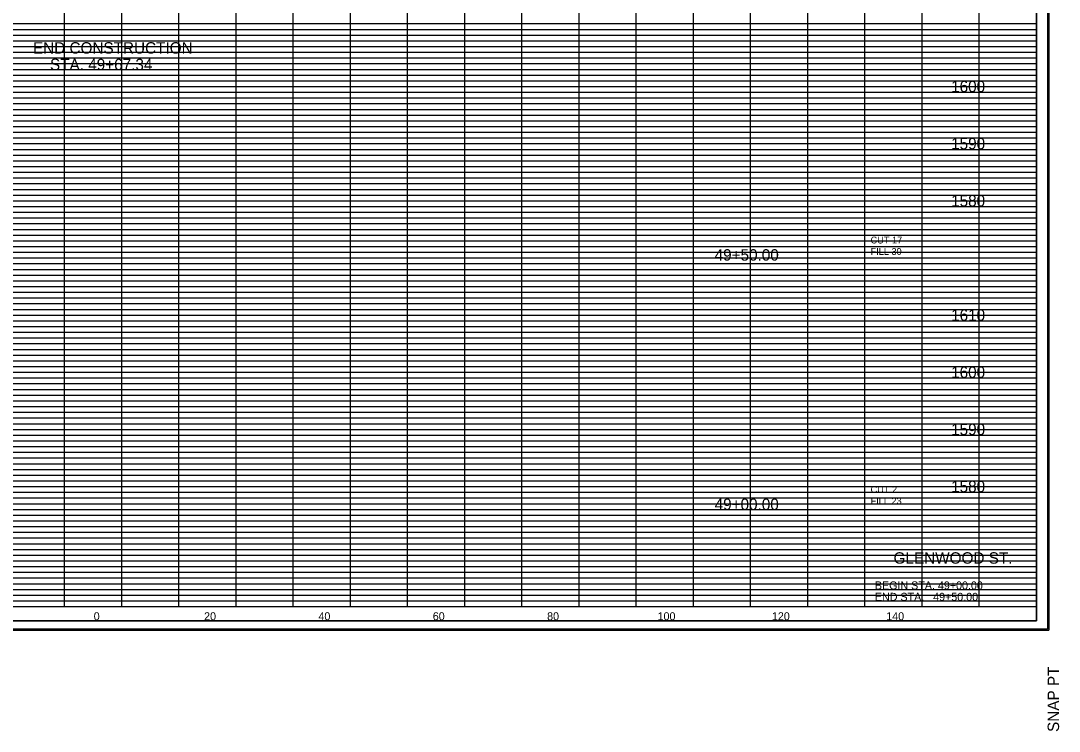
# Model space of a CAD drawing. Extents: x 980 to 1324, y 978 to 1497.
# Drawn here: x 1142.3 to 1324, y 1248.2 to 1372.5 of the extents above; entities that cross this region are included whole.
import ezdxf

# ---------------------------------------------------------------- set-up
doc = ezdxf.new("R2010")
doc.units = 0
for name, color, linetype in [('DESIGN - SHEET - Corner Text', 7, 'Continuous'), ('DESIGN - SHEET - Light Grid', 7, 'Continuous'), ('DESIGN - SHEET - Linework', 7, 'Continuous'), ('DESIGN - SHEET - Plot Shape', 7, 'Continuous'), ('DESIGN - TYPICAL - Text', 7, 'Continuous')]:
    doc.layers.add(name, color=color, linetype=linetype)

# ---------------------------------------------------------------- blocks, each defined once
blk = doc.blocks.new('XSTSHT')
at = {"layer": 'DESIGN - SHEET - Light Grid'}
for p, q in [((8, 10.2), (16, 10.2)), ((16, 10.2), (24, 10.2)), ((24, 10.2), (32, 10.2)), ((8, 10.1), (16, 10.1)), ((16, 10.1), (24, 10.1)), ((24, 10.1), (32, 10.1)), ((8, 9.9), (16, 9.9)), ((16, 9.9), (24, 9.9)), ((24, 9.9), (32, 9.9)), ((8, 9.8), (16, 9.8)), ((8, 9.7), (16, 9.7)), ((16, 9.8), (24, 9.8)), ((16, 9.7), (24, 9.7)), ((24, 9.8), (32, 9.8)), ((24, 9.7), (32, 9.7)), ((8, 9.6), (16, 9.6)), ((8, 9.5), (16, 9.5)), ((16, 9.6), (24, 9.6)), ((16, 9.5), (24, 9.5)), ((24, 9.6), (32, 9.6)), ((24, 9.5), (32, 9.5)), ((8, 9.4), (16, 9.4)), ((8, 9.3), (16, 9.3)), ((16, 9.4), (24, 9.4)), ((16, 9.3), (24, 9.3)), ((24, 9.4), (32, 9.4)), ((24, 9.3), (32, 9.3)), ((8, 9.2), (16, 9.2)), ((8, 9.1), (16, 9.1)), ((16, 9.2), (24, 9.2)), ((16, 9.1), (24, 9.1)), ((24, 9.2), (32, 9.2)), ((24, 9.1), (32, 9.1)), ((8, 8.9), (16, 8.9)), ((8, 8.8), (16, 8.8)), ((16, 8.9), (24, 8.9)), ((16, 8.8), (24, 8.8)), ((24, 8.9), (32, 8.9)), ((24, 8.8), (32, 8.8)), ((8, 8.7), (16, 8.7)), ((8, 8.6), (16, 8.6)), ((16, 8.7), (24, 8.7)), ((16, 8.6), (24, 8.6)), ((24, 8.7), (32, 8.7)), ((24, 8.6), (32, 8.6)), ((8, 8.5), (16, 8.5)), ((8, 8.4), (16, 8.4)), ((16, 8.5), (24, 8.5)), ((16, 8.4), (24, 8.4)), ((24, 8.5), (32, 8.5)), ((24, 8.4), (32, 8.4)), ((8, 8.3), (16, 8.3)), ((8, 8.2), (16, 8.2)), ((16, 8.3), (24, 8.3)), ((16, 8.2), (24, 8.2)), ((24, 8.3), (32, 8.3)), ((24, 8.2), (32, 8.2)), ((8, 8.1), (16, 8.1)), ((16, 8.1), (24, 8.1)), ((24, 8.1), (32, 8.1)), ((8, 7.9), (16, 7.9)), ((16, 7.9), (24, 7.9)), ((24, 7.9), (32, 7.9)), ((8, 7.8), (16, 7.8)), ((8, 7.7), (16, 7.7)), ((16, 7.8), (24, 7.8)), ((16, 7.7), (24, 7.7)), ((24, 7.8), (32, 7.8)), ((24, 7.7), (32, 7.7)), ((8, 7.6), (16, 7.6)), ((8, 7.5), (16, 7.5)), ((16, 7.6), (24, 7.6)), ((16, 7.5), (24, 7.5)), ((24, 7.6), (32, 7.6)), ((24, 7.5), (32, 7.5)), ((8, 7.4), (16, 7.4)), ((8, 7.3), (16, 7.3)), ((16, 7.4), (24, 7.4)), ((16, 7.3), (24, 7.3)), ((24, 7.4), (32, 7.4)), ((24, 7.3), (32, 7.3)), ((8, 7.2), (16, 7.2)), ((8, 7.1), (16, 7.1)), ((16, 7.2), (24, 7.2)), ((16, 7.1), (24, 7.1)), ((24, 7.2), (32, 7.2)), ((24, 7.1), (32, 7.1)), ((8, 6.9), (16, 6.9)), ((8, 6.8), (16, 6.8)), ((16, 6.9), (24, 6.9)), ((16, 6.8), (24, 6.8)), ((24, 6.9), (32, 6.9)), ((24, 6.8), (32, 6.8)), ((8, 6.7), (16, 6.7)), ((8, 6.6), (16, 6.6)), ((16, 6.7), (24, 6.7)), ((16, 6.6), (24, 6.6)), ((24, 6.7), (32, 6.7)), ((24, 6.6), (32, 6.6)), ((8, 6.5), (16, 6.5)), ((8, 6.4), (16, 6.4)), ((16, 6.5), (24, 6.5)), ((16, 6.4), (24, 6.4)), ((24, 6.5), (32, 6.5)), ((24, 6.4), (32, 6.4)), ((8, 6.3), (16, 6.3)), ((8, 6.2), (16, 6.2)), ((16, 6.3), (24, 6.3)), ((16, 6.2), (24, 6.2)), ((24, 6.3), (32, 6.3)), ((24, 6.2), (32, 6.2)), ((8, 6.1), (16, 6.1)), ((16, 6.1), (24, 6.1)), ((24, 6.1), (32, 6.1)), ((8, 5.9), (16, 5.9)), ((16, 5.9), (24, 5.9)), ((24, 5.9), (32, 5.9)), ((8, 5.8), (16, 5.8)), ((8, 5.7), (16, 5.7)), ((16, 5.8), (24, 5.8)), ((16, 5.7), (24, 5.7)), ((24, 5.8), (32, 5.8)), ((24, 5.7), (32, 5.7)), ((8, 5.6), (16, 5.6)), ((8, 5.5), (16, 5.5)), ((16, 5.6), (24, 5.6)), ((16, 5.5), (24, 5.5)), ((24, 5.6), (32, 5.6)), ((24, 5.5), (32, 5.5)), ((8, 5.4), (16, 5.4)), ((8, 5.3), (16, 5.3)), ((16, 5.4), (24, 5.4)), ((16, 5.3), (24, 5.3)), ((24, 5.4), (32, 5.4)), ((24, 5.3), (32, 5.3)), ((8, 5.2), (16, 5.2)), ((8, 5.1), (16, 5.1)), ((16, 5.2), (24, 5.2)), ((16, 5.1), (24, 5.1)), ((24, 5.2), (32, 5.2)), ((24, 5.1), (32, 5.1)), ((8, 4.9), (16, 4.9)), ((8, 4.8), (16, 4.8)), ((16, 4.9), (24, 4.9)), ((16, 4.8), (24, 4.8)), ((24, 4.9), (32, 4.9)), ((24, 4.8), (32, 4.8)), ((8, 4.7), (16, 4.7)), ((8, 4.6), (16, 4.6)), ((16, 4.7), (24, 4.7)), ((16, 4.6), (24, 4.6)), ((24, 4.7), (32, 4.7)), ((24, 4.6), (32, 4.6)), ((8, 4.5), (16, 4.5)), ((8, 4.4), (16, 4.4)), ((16, 4.5), (24, 4.5)), ((16, 4.4), (24, 4.4)), ((24, 4.5), (32, 4.5)), ((24, 4.4), (32, 4.4)), ((8, 4.3), (16, 4.3)), ((8, 4.2), (16, 4.2)), ((16, 4.3), (24, 4.3)), ((16, 4.2), (24, 4.2)), ((24, 4.3), (32, 4.3)), ((24, 4.2), (32, 4.2)), ((8, 4.1), (16, 4.1)), ((16, 4.1), (24, 4.1)), ((24, 4.1), (32, 4.1)), ((8, 3.9), (16, 3.9)), ((16, 3.9), (24, 3.9)), ((24, 3.9), (32, 3.9)), ((8, 3.8), (16, 3.8)), ((8, 3.7), (16, 3.7)), ((16, 3.8), (24, 3.8)), ((16, 3.7), (24, 3.7)), ((24, 3.8), (32, 3.8)), ((24, 3.7), (32, 3.7)), ((8, 3.6), (16, 3.6)), ((8, 3.5), (16, 3.5)), ((16, 3.6), (24, 3.6)), ((16, 3.5), (24, 3.5)), ((24, 3.6), (32, 3.6)), ((24, 3.5), (32, 3.5)), ((8, 3.4), (16, 3.4)), ((8, 3.3), (16, 3.3)), ((16, 3.4), (24, 3.4)), ((16, 3.3), (24, 3.3)), ((24, 3.4), (32, 3.4)), ((24, 3.3), (32, 3.3)), ((8, 3.2), (16, 3.2)), ((8, 3.1), (16, 3.1)), ((16, 3.2), (24, 3.2)), ((16, 3.1), (24, 3.1)), ((24, 3.2), (32, 3.2)), ((24, 3.1), (32, 3.1)), ((8, 2.9), (16, 2.9)), ((8, 2.8), (16, 2.8)), ((16, 2.9), (24, 2.9)), ((16, 2.8), (24, 2.8)), ((24, 2.9), (32, 2.9)), ((24, 2.8), (32, 2.8)), ((8, 2.7), (16, 2.7)), ((8, 2.6), (16, 2.6)), ((16, 2.7), (24, 2.7)), ((16, 2.6), (24, 2.6)), ((24, 2.7), (32, 2.7)), ((24, 2.6), (32, 2.6)), ((8, 2.5), (16, 2.5)), ((8, 2.4), (16, 2.4)), ((16, 2.5), (24, 2.5)), ((16, 2.4), (24, 2.4)), ((24, 2.5), (32, 2.5)), ((24, 2.4), (32, 2.4)), ((8, 2.3), (16, 2.3)), ((8, 2.2), (16, 2.2)), ((16, 2.3), (24, 2.3)), ((16, 2.2), (24, 2.2)), ((24, 2.3), (32, 2.3)), ((24, 2.2), (32, 2.2)), ((8, 2.1), (16, 2.1)), ((16, 2.1), (24, 2.1)), ((24, 2.1), (32, 2.1)), ((8, 1.9), (16, 1.9)), ((16, 1.9), (24, 1.9)), ((24, 1.9), (32, 1.9)), ((8, 1.8), (16, 1.8)), ((8, 1.7), (16, 1.7)), ((16, 1.8), (24, 1.8)), ((16, 1.7), (24, 1.7)), ((24, 1.8), (32, 1.8)), ((24, 1.7), (32, 1.7)), ((8, 1.6), (16, 1.6)), ((8, 1.5), (16, 1.5)), ((16, 1.6), (24, 1.6)), ((16, 1.5), (24, 1.5)), ((24, 1.6), (32, 1.6)), ((24, 1.5), (32, 1.5)), ((8, 1.4), (16, 1.4)), ((8, 1.3), (16, 1.3)), ((16, 1.4), (24, 1.4)), ((16, 1.3), (24, 1.3)), ((24, 1.4), (32, 1.4)), ((24, 1.3), (32, 1.3)), ((8, 1.2), (16, 1.2)), ((8, 1.1), (16, 1.1)), ((16, 1.2), (24, 1.2)), ((16, 1.1), (24, 1.1)), ((24, 1.2), (32, 1.2)), ((24, 1.1), (32, 1.1)), ((8, 0.9), (16, 0.9)), ((8, 0.8), (16, 0.8)), ((16, 0.9), (24, 0.9)), ((16, 0.8), (24, 0.8)), ((24, 0.9), (32, 0.9)), ((24, 0.8), (32, 0.8)), ((8, 0.7), (16, 0.7)), ((8, 0.6), (16, 0.6)), ((16, 0.7), (24, 0.7)), ((16, 0.6), (24, 0.6)), ((24, 0.7), (32, 0.7)), ((24, 0.6), (32, 0.6)), ((8, 0.5), (16, 0.5)), ((8, 0.4), (16, 0.4)), ((16, 0.5), (24, 0.5)), ((16, 0.4), (24, 0.4)), ((24, 0.5), (32, 0.5)), ((24, 0.4), (32, 0.4)), ((8, 0.3), (16, 0.3)), ((8, 0.2), (16, 0.2)), ((16, 0.3), (24, 0.3)), ((16, 0.2), (24, 0.2)), ((24, 0.3), (32, 0.3)), ((24, 0.2), (32, 0.2)), ((8, 0.1), (16, 0.1)), ((16, 0.1), (24, 0.1)), ((24, 0.1), (32, 0.1))]:
    blk.add_line(p, q, dxfattribs=at)
at = {"layer": 'DESIGN - SHEET - Linework'}
for p, q in [((32.217, 21.414), (32.217, -0.414)), ((15, 0), (15, 21)), ((16, 0), (16, 21)), ((17, 0), (17, 21)), ((18, 0), (18, 21)), ((19, 0), (19, 21)), ((20, 0), (20, 21)), ((21, 0), (21, 21)), ((22, 0), (22, 21)), ((23, 0), (23, 21)), ((24, 0), (24, 21)), ((25, 0), (25, 21)), ((26, 0), (26, 21)), ((27, 0), (27, 21)), ((28, 0), (28, 20)), ((29, 0), (29, 20)), ((30, 0), (30, 20)), ((31, 0), (31, 20)), ((0, 10), (32, 10)), ((0, 9), (32, 9)), ((0, 8), (32, 8)), ((0, 7), (32, 7)), ((0, 6), (32, 6)), ((0, 5), (32, 5)), ((0, 4), (32, 4)), ((0, 3), (32, 3)), ((0, 2), (32, 2)), ((0, 1), (32, 1)), ((-1.823, -0.414), (32.217, -0.414))]:
    blk.add_line(p, q, dxfattribs=at)
blk.add_lwpolyline([(0, 21), (0, 0), (32, 0), (32, 21), (0, 21)], dxfattribs=at)
at = {"layer": 'DESIGN - SHEET - Plot Shape'}
for points in [[(-1.803, 21.394), (32.197, 21.394), (32.197, -0.394), (-1.803, -0.394)], [(-0.85, 21), (32, 21), (32, -0.25), (-0.85, -0.25)]]:
    blk.add_lwpolyline(points, close=True, dxfattribs=at)
at = {"layer": 'DESIGN - SHEET - Corner Text'}
blk.add_text('SNAP PT  ', height=0.2, rotation=90, dxfattribs=at).set_placement((32.397, -2.194))

msp = doc.modelspace()

# ---------------------------------------------------------------- linework, layer by layer
at = {"layer": 'DESIGN - SHEET - Plot Shape'}
msp.add_lwpolyline([(991.5, 1267.5), (1320, 1267.5), (1320, 1480), (991.5, 1480)], close=True, dxfattribs=at)

# ---------------------------------------------------------------- block references
at = {"layer": 'DESIGN - TYPICAL - Text', "xscale": 10, "yscale": 10}
msp.add_blockref('XSTSHT', (1000, 1270), dxfattribs=at)

# ---------------------------------------------------------------- texts
at = {"layer": 'DESIGN - SHEET - Corner Text'}
for s, height, p in [('GLENWOOD ST.', 2, (1295.02, 1277.5)), ('BEGIN STA. 49+00.00', 1.4, (1291.75, 1273)), ('END STA.   49+50.00', 1.4, (1291.75, 1271))]:
    msp.add_text(s, height=height, dxfattribs=at).set_placement(p)
at = {"layer": 'DESIGN - TYPICAL - Text'}
for s, height, p in [('END CONSTRUCTION', 2, (1144.48, 1366.75)), ('STA. 49+67.34', 2, (1147.46, 1363.85)), ('     1600     ', 2, (1301.37, 1360)), ('     1590     ', 2, (1301.37, 1350)), ('     1580     ', 2, (1301.37, 1340)), ('CUT 17', 1.2, (1291, 1333.53)), ('     49+50.00     ', 2, (1260, 1330.53)), ('FILL 30', 1.2, (1291, 1331.53)), ('     1610     ', 2, (1301.37, 1320)), ('     1600     ', 2, (1301.37, 1310)), ('     1590     ', 2, (1301.37, 1300)), ('     1580     ', 2, (1301.37, 1290)), ('CUT 2', 1.2, (1291, 1289.89)), ('     49+00.00     ', 2, (1260, 1286.89)), ('FILL 23', 1.2, (1291, 1287.89)), ('     0     ', 1.4, (1152.51, 1267.6)), ('     0     ', 1.4, (1152.51, 1267.6)), ('     20     ', 1.4, (1171.82, 1267.6)), ('     40     ', 1.4, (1191.82, 1267.6)), ('     60     ', 1.4, (1211.82, 1267.6)), ('     80     ', 1.4, (1231.82, 1267.6)), ('     100     ', 1.4, (1251.14, 1267.6)), ('     120     ', 1.4, (1271.14, 1267.6)), ('     140     ', 1.4, (1291.14, 1267.6))]:
    msp.add_text(s, height=height, dxfattribs=at).set_placement(p)

doc.saveas('drawing.dxf')
